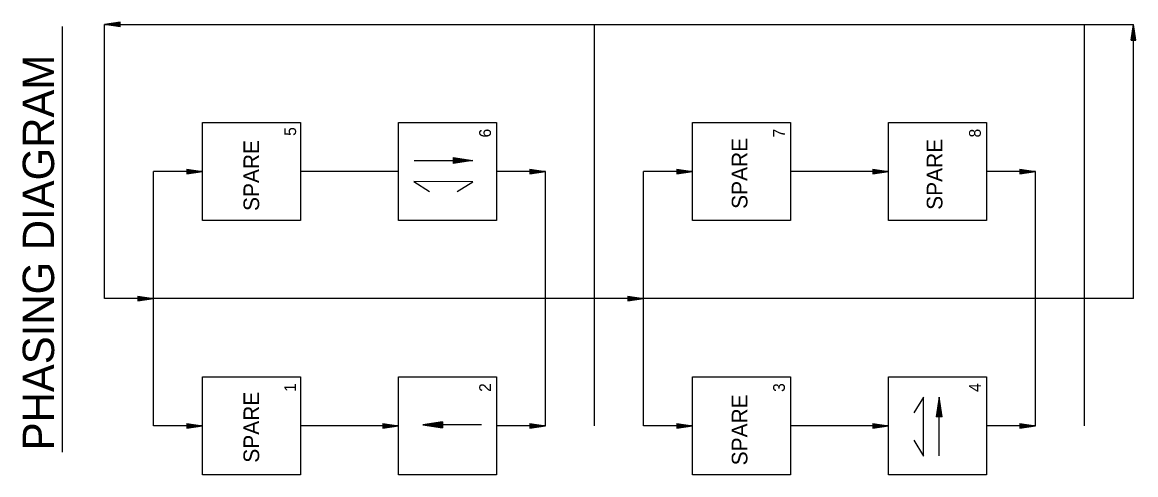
# Model space of a CAD drawing. Extents: x 610543 to 611161, y 419122 to 420064.
# Drawn here: x 610543.2 to 610827.3, y 419122.3 to 419237.9 of the extents above; entities that cross this region are included whole.
import ezdxf

# ---------------------------------------------------------------- set-up
doc = ezdxf.new("R2010")
doc.units = 0
doc.layers.add('Level 57', color=7, linetype='Continuous')
doc.layers.add('T_Drafting', color=7, linetype='Continuous')

msp = doc.modelspace()

# ---------------------------------------------------------------- linework, layer by layer
at = {"layer": 'Level 57'}
for p, q in [((610553.51, 419128.09), (610553.51, 419236.76)), ((610568.22, 419237.88), (610564.22, 419237.28)), ((610564.22, 419167.28), (610564.22, 419237.28)), ((610564.22, 419237.28), (610826.72, 419237.28)), ((610568.22, 419236.68), (610564.22, 419237.28)), ((610568.22, 419237.78), (610564.89, 419237.28)), ((610568.22, 419236.78), (610564.89, 419237.28)), ((610568.22, 419237.68), (610565.58, 419237.28)), ((610568.22, 419236.89), (610565.58, 419237.28)), ((610568.22, 419237.58), (610566.24, 419237.28)), ((610568.22, 419236.99), (610566.24, 419237.28)), ((610568.22, 419237.48), (610566.92, 419237.28)), ((610568.22, 419237.09), (610566.92, 419237.28)), ((610568.22, 419237.38), (610567.59, 419237.28)), ((610568.22, 419237.19), (610567.59, 419237.28)), ((610568.22, 419236.68), (610568.22, 419237.88)), ((610689.22, 419134.78), (610689.22, 419237.28)), ((610814.22, 419134.78), (610814.22, 419237.28)), ((610826.12, 419233.28), (610826.72, 419237.28)), ((610826.72, 419167.28), (610826.72, 419237.28)), ((610827.32, 419233.28), (610826.72, 419237.28)), ((610826.22, 419233.28), (610826.72, 419236.62)), ((610826.32, 419233.28), (610826.72, 419235.93)), ((610826.42, 419233.28), (610826.72, 419235.26)), ((610826.53, 419233.28), (610826.72, 419234.58)), ((610826.63, 419233.28), (610826.72, 419233.92)), ((610827.22, 419233.28), (610826.72, 419236.62)), ((610827.12, 419233.28), (610826.72, 419235.93)), ((610827.02, 419233.28), (610826.72, 419235.26)), ((610826.92, 419233.28), (610826.72, 419234.58)), ((610826.82, 419233.28), (610826.72, 419233.92)), ((610826.12, 419233.28), (610827.32, 419233.28)), ((610643.17, 419202.59), (610658.17, 419202.58)), ((610653.17, 419203.33), (610658.17, 419202.58)), ((610653.17, 419203.33), (610653.17, 419201.83)), ((610657.33, 419202.58), (610653.17, 419203.21)), ((610653.17, 419203.08), (610656.47, 419202.58)), ((610655.64, 419202.58), (610653.17, 419202.96)), ((610653.17, 419202.83), (610654.79, 419202.58)), ((610653.96, 419202.58), (610653.17, 419202.7)), ((610589.22, 419199.78), (610576.72, 419199.78)), ((610576.72, 419134.78), (610576.72, 419199.78)), ((610585.22, 419200.38), (610589.22, 419199.78)), ((610585.22, 419200.38), (610585.22, 419199.18)), ((610585.22, 419200.28), (610588.55, 419199.78)), ((610585.22, 419200.18), (610587.87, 419199.78)), ((610585.22, 419200.08), (610587.2, 419199.78)), ((610585.22, 419199.98), (610586.52, 419199.78)), ((610585.22, 419199.88), (610585.85, 419199.78)), ((610585.22, 419199.18), (610589.22, 419199.78)), ((610585.22, 419199.59), (610586.52, 419199.78)), ((610585.22, 419199.39), (610587.87, 419199.78)), ((610585.22, 419199.28), (610588.55, 419199.78)), ((610585.22, 419199.49), (610587.2, 419199.78)), ((610585.22, 419199.69), (610585.85, 419199.78)), ((610639.22, 419199.78), (610614.22, 419199.78)), ((610658.17, 419202.58), (610653.17, 419201.83)), ((610653.17, 419201.96), (610657.33, 419202.58)), ((610656.47, 419202.58), (610653.17, 419202.09)), ((610653.17, 419202.21), (610655.64, 419202.58)), ((610654.79, 419202.58), (610653.17, 419202.34)), ((610653.17, 419202.47), (610653.96, 419202.58)), ((610676.72, 419199.78), (610664.22, 419199.78)), ((610676.72, 419199.78), (610664.22, 419199.78)), ((610672.72, 419200.38), (610676.72, 419199.78)), ((610672.72, 419200.38), (610672.72, 419199.18)), ((610672.72, 419200.38), (610676.72, 419199.78)), ((610672.72, 419200.38), (610672.72, 419199.18)), ((610672.72, 419200.28), (610676.05, 419199.78)), ((610672.72, 419200.28), (610676.05, 419199.78)), ((610672.72, 419200.18), (610675.37, 419199.78)), ((610672.72, 419200.18), (610675.37, 419199.78)), ((610672.72, 419200.08), (610674.7, 419199.78)), ((610672.72, 419200.08), (610674.7, 419199.78)), ((610672.72, 419199.98), (610674.02, 419199.78)), ((610672.72, 419199.98), (610674.02, 419199.78)), ((610672.72, 419199.88), (610673.35, 419199.78)), ((610672.72, 419199.88), (610673.35, 419199.78)), ((610672.72, 419199.18), (610676.72, 419199.78)), ((610672.72, 419199.59), (610674.02, 419199.78)), ((610672.72, 419199.39), (610675.37, 419199.78)), ((610672.72, 419199.28), (610676.05, 419199.78)), ((610672.72, 419199.49), (610674.7, 419199.78)), ((610672.72, 419199.69), (610673.35, 419199.78)), ((610672.72, 419199.18), (610676.72, 419199.78)), ((610672.72, 419199.59), (610674.02, 419199.78)), ((610672.72, 419199.39), (610675.37, 419199.78)), ((610672.72, 419199.28), (610676.05, 419199.78)), ((610672.72, 419199.49), (610674.7, 419199.78)), ((610672.72, 419199.69), (610673.35, 419199.78)), ((610676.72, 419134.78), (610676.72, 419199.78)), ((610701.72, 419134.78), (610701.72, 419199.78)), ((610714.22, 419199.78), (610701.72, 419199.78)), ((610710.22, 419200.38), (610714.22, 419199.78)), ((610710.22, 419200.38), (610710.22, 419199.18)), ((610710.22, 419200.28), (610713.55, 419199.78)), ((610710.22, 419200.18), (610712.87, 419199.78)), ((610710.22, 419200.08), (610712.2, 419199.78)), ((610710.22, 419199.98), (610711.52, 419199.78)), ((610710.22, 419199.88), (610710.85, 419199.78)), ((610710.22, 419199.18), (610714.22, 419199.78)), ((610710.22, 419199.59), (610711.52, 419199.78)), ((610710.22, 419199.39), (610712.87, 419199.78)), ((610710.22, 419199.28), (610713.55, 419199.78)), ((610710.22, 419199.49), (610712.2, 419199.78)), ((610710.22, 419199.69), (610710.85, 419199.78)), ((610764.22, 419199.78), (610739.22, 419199.78)), ((610760.22, 419200.38), (610764.22, 419199.78)), ((610760.22, 419200.38), (610760.22, 419199.18)), ((610760.22, 419200.28), (610763.55, 419199.78)), ((610760.22, 419200.18), (610762.87, 419199.78)), ((610760.22, 419200.08), (610762.2, 419199.78)), ((610760.22, 419199.98), (610761.52, 419199.78)), ((610760.22, 419199.88), (610760.85, 419199.78)), ((610760.22, 419199.18), (610764.22, 419199.78)), ((610760.22, 419199.59), (610761.52, 419199.78)), ((610760.22, 419199.39), (610762.87, 419199.78)), ((610760.22, 419199.28), (610763.55, 419199.78)), ((610760.22, 419199.49), (610762.2, 419199.78)), ((610760.22, 419199.69), (610760.85, 419199.78)), ((610801.72, 419199.78), (610789.22, 419199.78)), ((610797.72, 419200.38), (610801.72, 419199.78)), ((610797.72, 419200.38), (610797.72, 419199.18)), ((610797.72, 419200.28), (610801.05, 419199.78)), ((610797.72, 419200.18), (610800.37, 419199.78)), ((610797.72, 419200.08), (610799.7, 419199.78)), ((610797.72, 419199.98), (610799.02, 419199.78)), ((610797.72, 419199.88), (610798.35, 419199.78)), ((610797.72, 419199.18), (610801.72, 419199.78)), ((610797.72, 419199.59), (610799.02, 419199.78)), ((610797.72, 419199.39), (610800.37, 419199.78)), ((610797.72, 419199.28), (610801.05, 419199.78)), ((610797.72, 419199.49), (610799.7, 419199.78)), ((610797.72, 419199.69), (610798.35, 419199.78)), ((610801.72, 419134.78), (610801.72, 419199.78)), ((610826.72, 419167.28), (610564.22, 419167.28)), ((610572.72, 419167.88), (610576.72, 419167.28)), ((610572.72, 419167.88), (610572.72, 419166.68)), ((610572.72, 419167.78), (610576.05, 419167.28)), ((610572.72, 419167.68), (610575.37, 419167.28)), ((610572.72, 419167.58), (610574.7, 419167.28)), ((610572.72, 419167.48), (610574.02, 419167.28)), ((610572.72, 419167.38), (610573.35, 419167.28)), ((610572.72, 419166.68), (610576.72, 419167.28)), ((610572.72, 419167.09), (610574.02, 419167.28)), ((610572.72, 419166.89), (610575.37, 419167.28)), ((610572.72, 419166.78), (610576.05, 419167.28)), ((610572.72, 419166.99), (610574.7, 419167.28)), ((610572.72, 419167.19), (610573.35, 419167.28)), ((610697.72, 419167.88), (610701.72, 419167.28)), ((610697.72, 419167.88), (610697.72, 419166.68)), ((610697.72, 419167.78), (610701.05, 419167.28)), ((610697.72, 419167.68), (610700.37, 419167.28)), ((610697.72, 419167.58), (610699.7, 419167.28)), ((610697.72, 419167.48), (610699.02, 419167.28)), ((610697.72, 419167.38), (610698.35, 419167.28)), ((610697.72, 419166.68), (610701.72, 419167.28)), ((610697.72, 419167.09), (610699.02, 419167.28)), ((610697.72, 419166.89), (610700.37, 419167.28)), ((610697.72, 419166.78), (610701.05, 419167.28)), ((610697.72, 419166.99), (610699.7, 419167.28)), ((610697.72, 419167.19), (610698.35, 419167.28)), ((610777.18, 419142.12), (610776.42, 419137.12)), ((610776.54, 419137.12), (610777.18, 419141.28)), ((610777.18, 419140.42), (610776.67, 419137.12)), ((610777.14, 419127.12), (610777.18, 419142.12)), ((610777.92, 419137.12), (610777.18, 419142.12)), ((610777.18, 419141.28), (610777.79, 419137.12)), ((610777.66, 419137.12), (610777.18, 419140.42)), ((610776.79, 419137.12), (610777.17, 419139.59)), ((610777.17, 419138.74), (610776.92, 419137.12)), ((610777.05, 419137.12), (610777.17, 419137.91)), ((610777.17, 419139.59), (610777.54, 419137.12)), ((610777.41, 419137.12), (610777.17, 419138.74)), ((610777.17, 419137.91), (610777.28, 419137.12)), ((610589.22, 419134.78), (610576.72, 419134.78)), ((610585.22, 419135.38), (610589.22, 419134.78)), ((610585.22, 419135.38), (610585.22, 419134.18)), ((610585.22, 419135.28), (610588.55, 419134.78)), ((610585.22, 419135.18), (610587.87, 419134.78)), ((610585.22, 419135.08), (610587.2, 419134.78)), ((610585.22, 419134.98), (610586.52, 419134.78)), ((610585.22, 419134.88), (610585.85, 419134.78)), ((610585.22, 419134.18), (610589.22, 419134.78)), ((610585.22, 419134.59), (610586.52, 419134.78)), ((610585.22, 419134.39), (610587.87, 419134.78)), ((610585.22, 419134.28), (610588.55, 419134.78)), ((610585.22, 419134.49), (610587.2, 419134.78)), ((610585.22, 419134.69), (610585.85, 419134.78)), ((610639.22, 419134.78), (610614.22, 419134.78)), ((610635.22, 419135.38), (610639.22, 419134.78)), ((610635.22, 419135.38), (610635.22, 419134.18)), ((610635.22, 419135.28), (610638.55, 419134.78)), ((610635.22, 419135.18), (610637.87, 419134.78)), ((610635.22, 419135.08), (610637.2, 419134.78)), ((610635.22, 419134.98), (610636.52, 419134.78)), ((610635.22, 419134.88), (610635.85, 419134.78)), ((610635.22, 419134.18), (610639.22, 419134.78)), ((610635.22, 419134.59), (610636.52, 419134.78)), ((610635.22, 419134.39), (610637.87, 419134.78)), ((610635.22, 419134.28), (610638.55, 419134.78)), ((610635.22, 419134.49), (610637.2, 419134.78)), ((610635.22, 419134.69), (610635.85, 419134.78)), ((610650.4, 419135.8), (610645.4, 419135.04)), ((610660.4, 419135.08), (610645.4, 419135.04)), ((610645.4, 419135.04), (610650.41, 419134.3)), ((610646.24, 419135.04), (610650.4, 419135.68)), ((610650.41, 419134.43), (610646.24, 419135.04)), ((610650.4, 419135.55), (610647.1, 419135.04)), ((610647.1, 419135.04), (610650.41, 419134.56)), ((610647.93, 419135.05), (610650.4, 419135.43)), ((610650.4, 419134.68), (610647.93, 419135.05)), ((610650.4, 419135.3), (610648.78, 419135.05)), ((610648.78, 419135.05), (610650.4, 419134.81)), ((610649.61, 419135.05), (610650.4, 419135.17)), ((610650.4, 419134.94), (610649.61, 419135.05)), ((610650.4, 419135.8), (610650.41, 419134.3)), ((610676.72, 419134.78), (610664.22, 419134.78)), ((610672.72, 419135.38), (610676.72, 419134.78)), ((610672.72, 419135.38), (610672.72, 419134.18)), ((610672.72, 419135.28), (610676.05, 419134.78)), ((610672.72, 419135.18), (610675.37, 419134.78)), ((610672.72, 419135.08), (610674.7, 419134.78)), ((610672.72, 419134.98), (610674.02, 419134.78)), ((610672.72, 419134.88), (610673.35, 419134.78)), ((610672.72, 419134.18), (610676.72, 419134.78)), ((610672.72, 419134.59), (610674.02, 419134.78)), ((610672.72, 419134.39), (610675.37, 419134.78)), ((610672.72, 419134.28), (610676.05, 419134.78)), ((610672.72, 419134.49), (610674.7, 419134.78)), ((610672.72, 419134.69), (610673.35, 419134.78)), ((610714.22, 419134.78), (610701.72, 419134.78)), ((610710.22, 419135.38), (610714.22, 419134.78)), ((610710.22, 419135.38), (610710.22, 419134.18)), ((610710.22, 419135.28), (610713.55, 419134.78)), ((610710.22, 419135.18), (610712.87, 419134.78)), ((610710.22, 419135.08), (610712.2, 419134.78)), ((610710.22, 419134.98), (610711.52, 419134.78)), ((610710.22, 419134.88), (610710.85, 419134.78)), ((610710.22, 419134.18), (610714.22, 419134.78)), ((610710.22, 419134.59), (610711.52, 419134.78)), ((610710.22, 419134.39), (610712.87, 419134.78)), ((610710.22, 419134.28), (610713.55, 419134.78)), ((610710.22, 419134.49), (610712.2, 419134.78)), ((610710.22, 419134.69), (610710.85, 419134.78)), ((610764.22, 419134.78), (610739.22, 419134.78)), ((610760.22, 419135.38), (610764.22, 419134.78)), ((610760.22, 419135.38), (610760.22, 419134.18)), ((610760.22, 419135.28), (610763.55, 419134.78)), ((610760.22, 419135.18), (610762.87, 419134.78)), ((610760.22, 419135.08), (610762.2, 419134.78)), ((610760.22, 419134.98), (610761.52, 419134.78)), ((610760.22, 419134.88), (610760.85, 419134.78)), ((610760.22, 419134.18), (610764.22, 419134.78)), ((610760.22, 419134.59), (610761.52, 419134.78)), ((610760.22, 419134.39), (610762.87, 419134.78)), ((610760.22, 419134.28), (610763.55, 419134.78)), ((610760.22, 419134.49), (610762.2, 419134.78)), ((610760.22, 419134.69), (610760.85, 419134.78)), ((610777.92, 419137.12), (610776.42, 419137.12)), ((610801.72, 419134.78), (610789.22, 419134.78)), ((610797.72, 419135.38), (610801.72, 419134.78)), ((610797.72, 419135.38), (610797.72, 419134.18)), ((610797.72, 419135.28), (610801.05, 419134.78)), ((610797.72, 419135.18), (610800.37, 419134.78)), ((610797.72, 419135.08), (610799.7, 419134.78)), ((610797.72, 419134.98), (610799.02, 419134.78)), ((610797.72, 419134.88), (610798.35, 419134.78)), ((610797.72, 419134.18), (610801.72, 419134.78)), ((610797.72, 419134.59), (610799.02, 419134.78)), ((610797.72, 419134.39), (610800.37, 419134.78)), ((610797.72, 419134.28), (610801.05, 419134.78)), ((610797.72, 419134.49), (610799.7, 419134.78)), ((610797.72, 419134.69), (610798.35, 419134.78))]:
    msp.add_line(p, q, dxfattribs=at)
for points in [[(610589.22, 419187.28), (610589.22, 419212.28), (610614.22, 419212.28), (610614.22, 419187.28)], [(610639.22, 419187.28), (610639.22, 419212.28), (610664.22, 419212.28), (610664.22, 419187.28)], [(610714.22, 419212.28), (610739.22, 419212.28), (610739.22, 419187.28), (610714.22, 419187.28)], [(610764.22, 419187.28), (610764.22, 419212.28), (610789.22, 419212.28), (610789.22, 419187.28)], [(610589.22, 419122.28), (610589.22, 419147.28), (610614.22, 419147.28), (610614.22, 419122.28)], [(610639.22, 419122.28), (610639.22, 419147.28), (610664.22, 419147.28), (610664.22, 419122.28)], [(610739.22, 419122.28), (610714.22, 419122.28), (610714.22, 419147.28), (610739.22, 419147.28)], [(610764.22, 419122.28), (610764.22, 419147.28), (610789.22, 419147.28), (610789.22, 419122.28)]]:
    msp.add_lwpolyline(points, close=True, dxfattribs=at)
for points in [[(610654.14, 419194.64), (610658.15, 419197.12), (610643.15, 419197.17), (610647.14, 419194.65)], [(610770.68, 419131.08), (610773.17, 419127.07), (610773.21, 419142.07), (610770.7, 419138.08)]]:
    msp.add_lwpolyline(points, dxfattribs=at)

# ---------------------------------------------------------------- texts
for s, height, p in [('PHASING DIAGRAM', 8, (610551.33, 419128.53)), ('5', 3, (610613.08, 419208.85)), ('6', 3, (610662.8, 419208.44)), ('7', 3, (610737.8, 419208.44)), ('8', 3, (610787.8, 419208.44)), ('1', 3, (610613.08, 419143.44)), ('2', 3, (610662.8, 419143.44)), ('3', 3, (610737.8, 419143.44)), ('4', 3, (610787.8, 419143.44))]:
    msp.add_text(s, height=height, rotation=90, dxfattribs=at).set_placement(p)
at = {"layer": 'T_Drafting'}
for p in [(610603.65, 419189.67), (610728.24, 419190.21), (610778, 419189.96), (610603.65, 419125.36), (610728.24, 419124.69)]:
    msp.add_text('SPARE', height=4, rotation=90, dxfattribs=at).set_placement(p)

doc.saveas('drawing.dxf')
